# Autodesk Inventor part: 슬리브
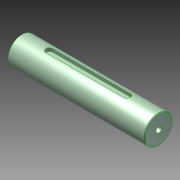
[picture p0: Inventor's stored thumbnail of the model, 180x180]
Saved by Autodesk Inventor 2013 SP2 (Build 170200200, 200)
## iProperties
Created: 2024-07
Part Number: 슬리브
Material: Generic
Document SubType Name: Modeling
Designer: 601
Density: 1 g/cm^3
Author: 601
변환 표준: STEP AP214IS
전처리기: Build: 200, Release: 2013 SP2 Update 6 - Date: Thu 07/17/2014
전송 단위: 밀리미터
불확실성: 0.01
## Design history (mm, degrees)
node "슬리브1"
node "솔리드1"
node "기준1"
